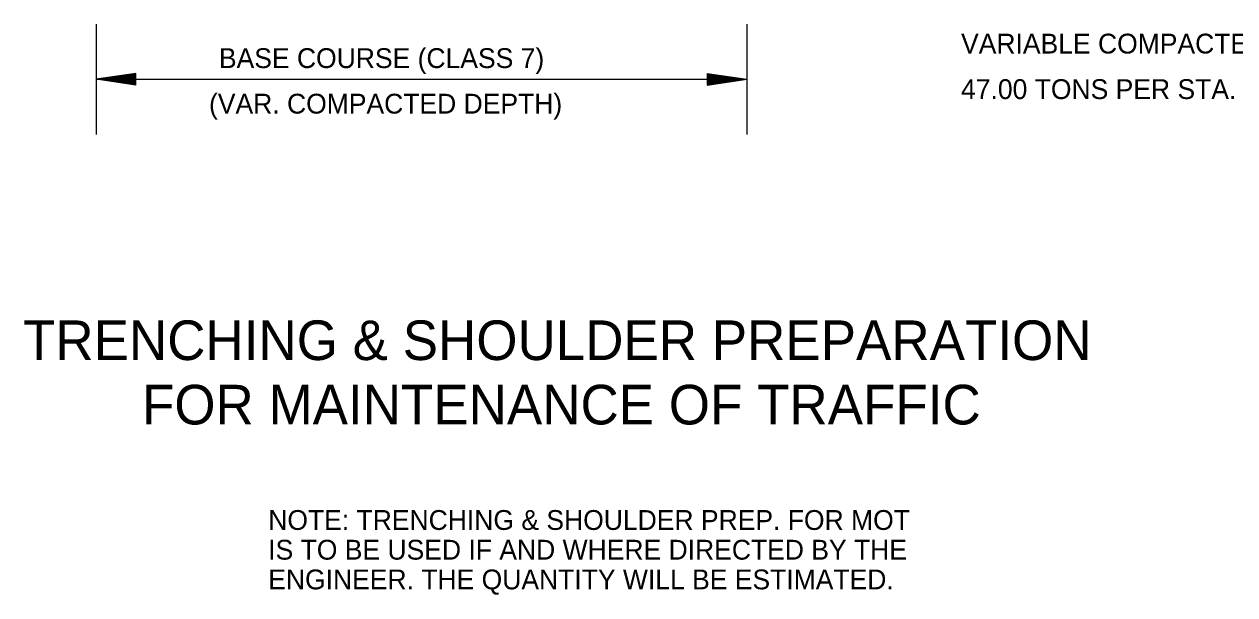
# Model space of a CAD drawing. Extents: x 1929624 to 1935547, y 596315 to 605721.
# Drawn here: x 1932771.9 to 1933138.6, y 604122.9 to 604295.7 of the extents above; entities that cross this region are included whole.
import ezdxf

# ---------------------------------------------------------------- set-up
doc = ezdxf.new("R2010")
doc.units = 0
doc.layers.add('Default', color=7, linetype='Continuous')
doc.layers.add('R_Annotation', color=7, linetype='Continuous')

msp = doc.modelspace()

# ---------------------------------------------------------------- linework, layer by layer
at = {"layer": 'Default'}
for p, q in [((1932793.72, 604295.7), (1932793.72, 604262.34)), ((1932990.74, 604295.7), (1932990.74, 604262.34)), ((1932805.72, 604280.82), (1932793.72, 604279.02)), ((1932793.72, 604279.02), (1932990.74, 604279.02)), ((1932805.72, 604277.22), (1932793.72, 604279.02)), ((1932805.72, 604280.52), (1932795.72, 604279.02)), ((1932805.72, 604277.52), (1932795.72, 604279.02)), ((1932805.72, 604280.21), (1932797.79, 604279.02)), ((1932805.72, 604277.83), (1932797.79, 604279.02)), ((1932805.72, 604279.91), (1932799.79, 604279.02)), ((1932805.72, 604278.13), (1932799.79, 604279.02)), ((1932805.72, 604279.61), (1932801.82, 604279.02)), ((1932805.72, 604278.44), (1932801.82, 604279.02)), ((1932805.72, 604279.3), (1932803.82, 604279.02)), ((1932805.72, 604278.74), (1932803.82, 604279.02)), ((1932805.72, 604277.22), (1932805.72, 604280.82)), ((1932978.74, 604280.82), (1932990.74, 604279.02)), ((1932978.74, 604280.82), (1932978.74, 604277.22)), ((1932978.74, 604280.52), (1932988.74, 604279.02)), ((1932978.74, 604280.21), (1932986.67, 604279.02)), ((1932978.74, 604279.91), (1932984.67, 604279.02)), ((1932978.74, 604279.6), (1932982.64, 604279.02)), ((1932978.74, 604279.3), (1932980.64, 604279.02)), ((1932978.74, 604277.22), (1932990.74, 604279.02)), ((1932978.74, 604278.43), (1932982.64, 604279.02)), ((1932978.74, 604277.83), (1932986.67, 604279.02)), ((1932978.74, 604277.52), (1932988.74, 604279.02)), ((1932978.74, 604278.13), (1932984.67, 604279.02)), ((1932978.74, 604278.74), (1932980.64, 604279.02))]:
    msp.add_line(p, q, dxfattribs=at)

# ---------------------------------------------------------------- texts
for s, height, p in [('VARIABLE COMPACTED DEPTH', 6, (1933055.68, 604286.83)), ('BASE COURSE (CLASS 7)', 6, (1932830.88, 604282.43)), ('47.00 TONS PER STA.', 6, (1933055.68, 604273.04)), ('(VAR. COMPACTED DEPTH)', 6, (1932827.88, 604268.64)), ('TRENCHING & SHOULDER PREPARATION', 12, (1932771.54, 604194)), ('FOR MAINTENANCE OF TRAFFIC', 12, (1932807.57, 604174.5))]:
    msp.add_text(s, height=height, dxfattribs=at).set_placement(p)
at = {"layer": 'R_Annotation'}
for s, p in [('NOTE: TRENCHING & SHOULDER PREP. FOR MOT', (1932845.82, 604142.56)), ('IS TO BE USED IF AND WHERE DIRECTED BY THE', (1932845.82, 604133.56)), ('ENGINEER. THE QUANTITY WILL BE ESTIMATED.', (1932845.82, 604124.56))]:
    msp.add_text(s, height=6, rotation=360, dxfattribs=at).set_placement(p)

doc.saveas('drawing.dxf')
